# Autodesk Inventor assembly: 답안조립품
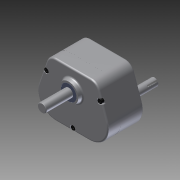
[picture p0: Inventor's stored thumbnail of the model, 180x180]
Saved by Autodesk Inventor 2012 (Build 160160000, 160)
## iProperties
Created: 2014-12
Part Number: 답안조립품
Document SubType Name: Assembly
Designer: Owner
Author: Owner
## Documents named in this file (14)
- C:\Documents and Settings\Owner\바탕 화면\441208V1019\답안조립품.iam
- C:\Documents and Settings\Owner\바탕 화면\441208V1019\본체.ipt
- C:\Documents and Settings\Owner\바탕 화면\441208V1019\메인축.ipt
- C:\Documents and Settings\Owner\바탕 화면\441208V1019\메인기어.ipt
- C:\Documents and Settings\Owner\바탕 화면\441208V1019\키5x5.ipt
- C:\Documents and Settings\Owner\바탕 화면\441208V1019\베어링- 6202.ipt
- C:\Documents and Settings\Owner\바탕 화면\441208V1019\멈춤링.ipt
- C:\Documents and Settings\Owner\바탕 화면\441208V1019\베어링- 6203.ipt
- C:\Documents and Settings\Owner\바탕 화면\441208V1019\커버.ipt
- C:\Documents and Settings\Owner\바탕 화면\441208V1019\오일시일-D-15.ipt
- C:\Documents and Settings\Owner\바탕 화면\441208V1019\서브기어.ipt
- C:\Documents and Settings\Owner\바탕 화면\441208V1019\서브축.ipt
- C:\Documents and Settings\Owner\바탕 화면\441208V1019\M 5 x 35.ipt
- C:\Documents and Settings\Owner\바탕 화면\441208V1019\오일시일-D-17.ipt
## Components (15 placed, 6 different names)
1. KS B 2023 6202 - 15 x 35 x 11:1
2. KS B 1336 17 x 1:1
3. KS B 2023 6203 - 17 x 40 x 12:1
4. KS B 2023 6203 - 17 x 40 x 12:2
5. KS B 2023 6202 - 15 x 35 x 11:2
6. KS B 1336 17 x 1:2
7. KS B 1336 17 x 1:3
8. KS B 2023 6203 - 17 x 40 x 12:3
9. KS B 2023 6203 - 17 x 40 x 12:4
10. KS B 1003 - 미터 M 5 x 35:1 — 각도:8
11. KS B 1003 - 미터 M 5 x 35:2 — 각도:9
12. KS B 1003 - 미터 M 5 x 35:3 — 각도:7
13. KS B 2804 D D - 15 30 7:2
14. KS B 2804 D D - 15 30 7:3
15. KS B 2804 D D - 17 30 8:1
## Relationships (3: Angle 3)
- 각도:7 [Angle]: KS B 1003 - 미터 M 5 x 35:3
- 각도:8 [Angle]: KS B 1003 - 미터 M 5 x 35:1
- 각도:9 [Angle]: KS B 1003 - 미터 M 5 x 35:2
